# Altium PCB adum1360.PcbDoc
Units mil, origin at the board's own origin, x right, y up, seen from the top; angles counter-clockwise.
Board outline 2370 x 1680 mil, 2 copper layers (Top Layer, Bottom Layer); 20 components, 16 nets, 69 pads, 14 vias.
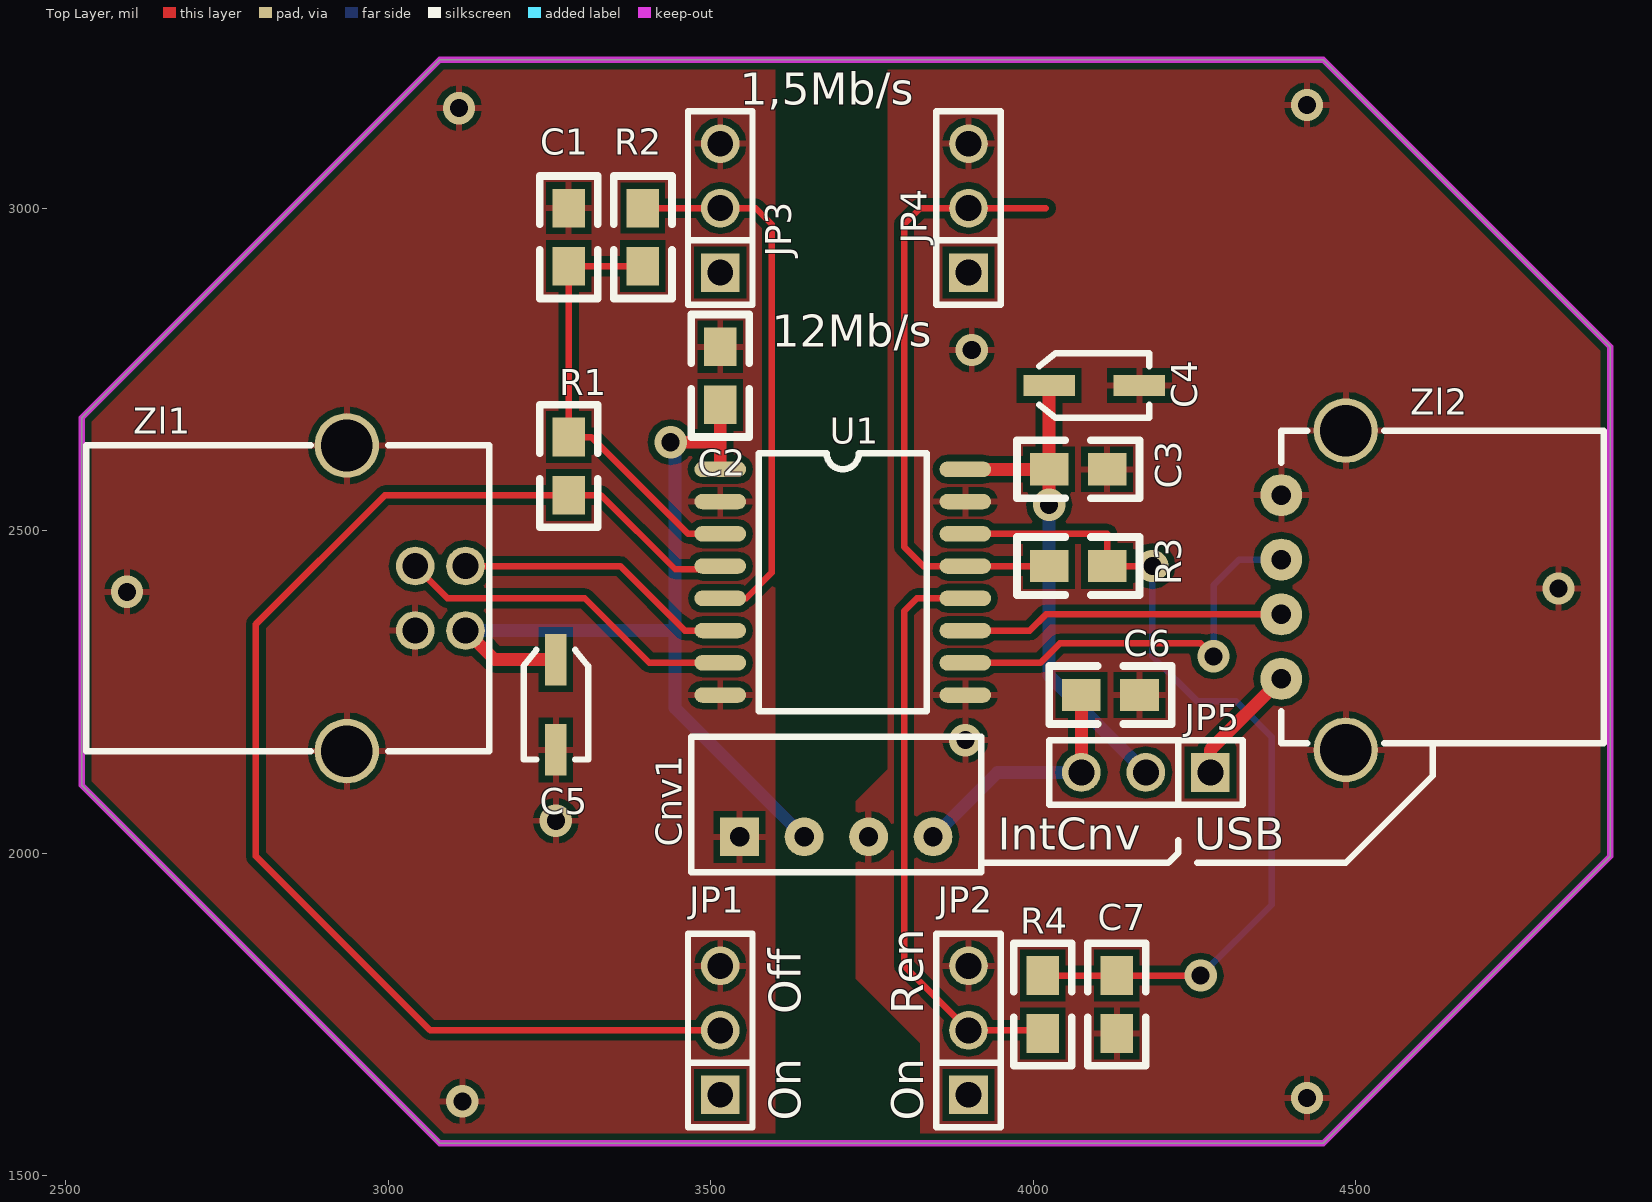
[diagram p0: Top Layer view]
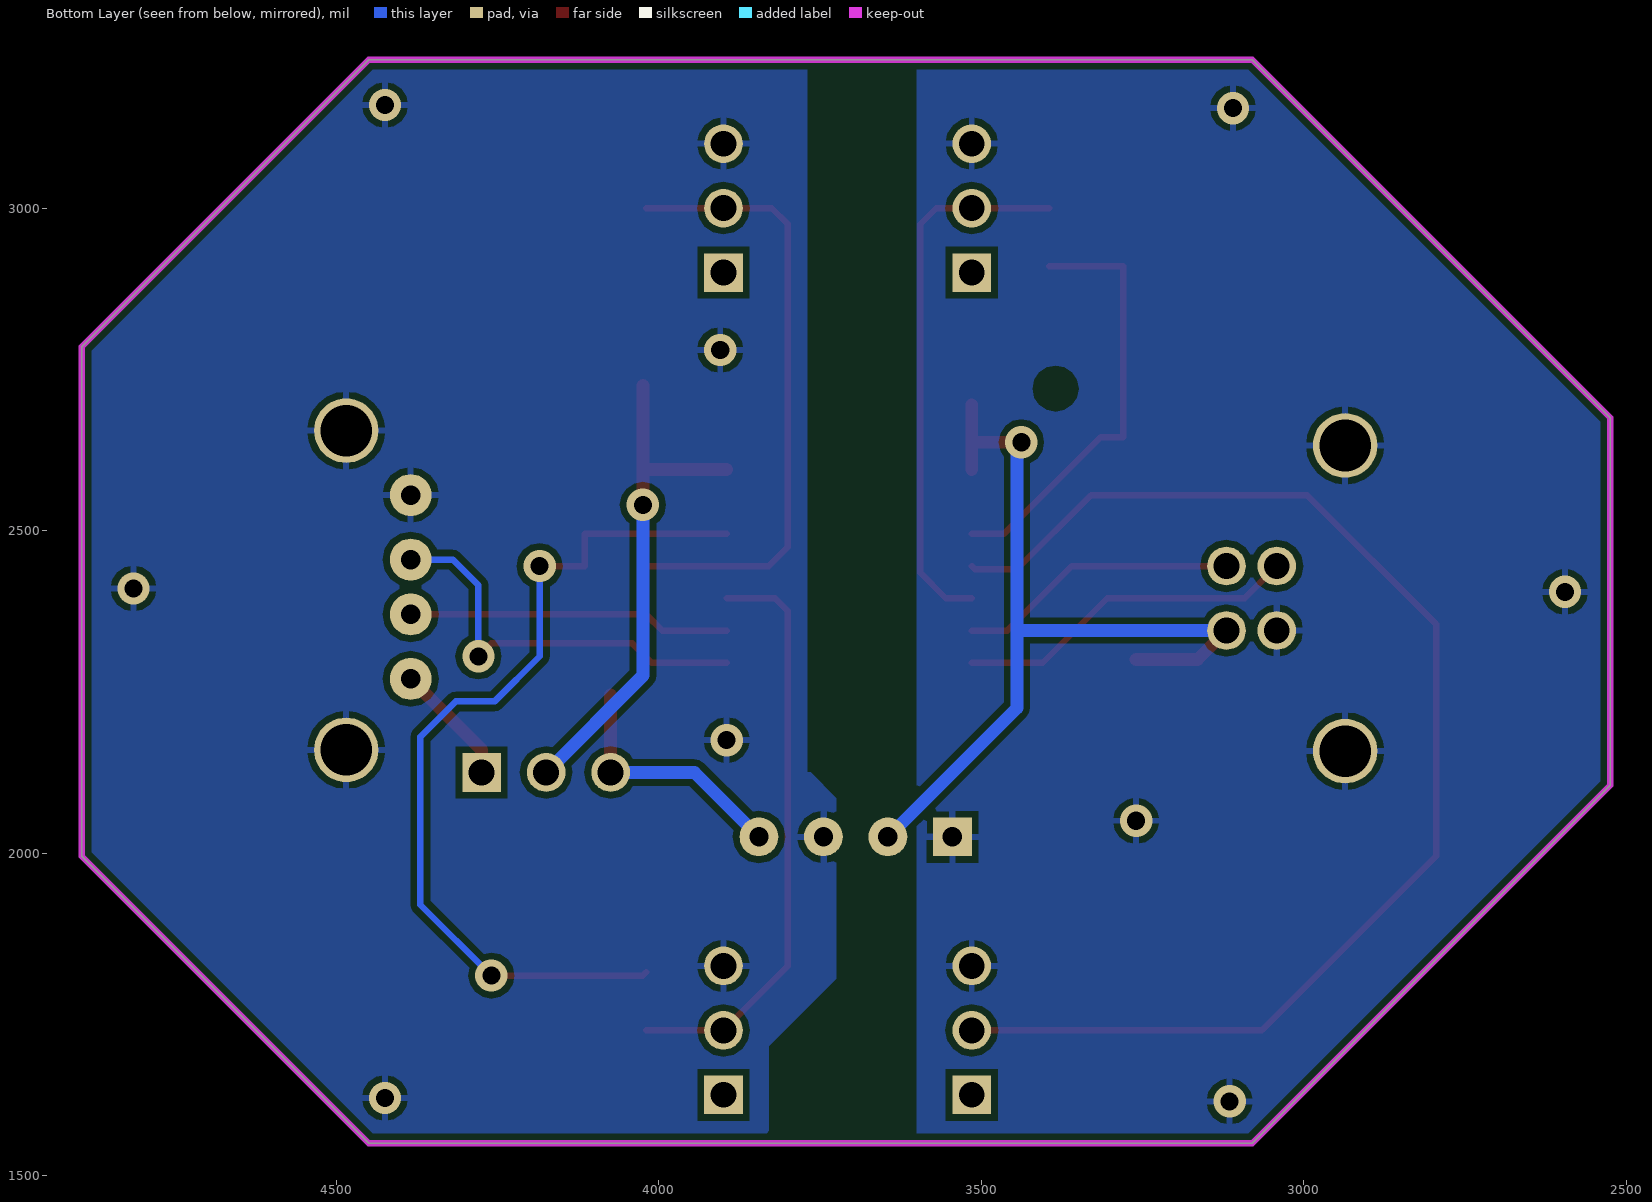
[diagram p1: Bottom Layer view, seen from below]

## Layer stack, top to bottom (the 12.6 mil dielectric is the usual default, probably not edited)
Top Layer: signal copper 1.4
Dielectric: dielectric 12.6, FR-4, Dk 4.8
Bottom Layer: signal copper 1.4

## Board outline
2525,2105 2525,2675 3080,3230 4450,3230 4895,2785 4895,1995 4450,1550 3080,1550

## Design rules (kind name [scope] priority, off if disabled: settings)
Clearance [All] p1: gap=10
PolygonConnect [All] p1: connectstyle=Relief reliefconductorwidth=10 reliefentries=4 polygonreliefangle="90 Angle"
RoutingVias [All] p1: holewidth=28 width=50 viastyle="Through Hole" minholewidth=28 minwidth=50 maxholewidth=28 maxwidth=50
SilkscreenOverComponentPads [All] p1: minsilkscreentomaskgap=10
SolderMaskExpansion [All] p1: expansion=4
Width Width_1 [InNet('VCC1')] p1: maxlimit=20 minlimit=15 preferedwidth=20
Width [InNet('VCC1')] p2: maxlimit=12 minlimit=10 preferedwidth=12 minimp=50.000000 maximp=50.000000 favimp=50.000000
27 further rules are at their usual default settings.

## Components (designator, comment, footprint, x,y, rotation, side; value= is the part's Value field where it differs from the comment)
C1 "100nF" 0805 3280,3000 r270 top
C2 "100nF" 0805 3515,2785 r270 top
C3 "100nF" 0805 4115,2595 r180 top
C4 "10uF" CE_SMD_W 4025,2725 r0 top
C5 "10uF" CE_SMD_W 3260,2300 r270 top
C6 "100nF" 0805 4165,2245 r180 top
C7 "100nF" 0805 4130,1810 r270 top
Cnv1 "AM1S-0505SZ" SIP4_AM1S 3545,2025 r0 top
JP1 "JP" sip-3 3515,1625 r90 top
JP2 "JP" sip-3 3900,1625 r90 top
JP3 "JP" sip-3 3515,2900 r90 top
JP4 "JP" sip-3 3900,2900 r90 top
JP5 "JP" sip-3 4275,2125 r180 top
R1 "10k" 0805 3280,2555 r90 top
R2 "10k" 0805 3395,3000 r270 top
R3 "10k" 0805 4025,2445 r0 top
R4 "10k" 0805 4015,1720 r90 top
U1 "ADUM3160" SOL-16 3515,2595 r0 top
Zl1 "USB_B" USB_B 3120,2345 r180 top
Zl2 "USB_A" USB_A 4385,2270 r0 top

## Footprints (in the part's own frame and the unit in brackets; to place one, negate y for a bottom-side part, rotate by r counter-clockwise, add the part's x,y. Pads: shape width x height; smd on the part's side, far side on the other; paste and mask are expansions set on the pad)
0805 [mil]
  rect 60x50 smd: 1(0,0) 2(90,0)
  silkscreen extent -50,-45 140,45
CE_SMD_W [mil]
  rect 80x33 smd: 1(0,0) 2(140,0)
  silkscreen extent -15,-50 155,50
SIP4_AM1S [mil]
  rect 60x60 hole 30: 1(0,0)
  round 60 hole 30: 2(100,0) 3(200,0) 4(300,0)
  silkscreen extent -75,-55 375,155
sip-3 [mil]
  rect 60x60 hole 40: 1(0,0)
  round 60 hole 40: 2(100,0) 3(200,0)
  silkscreen extent -50,-50 250,50
SOL-16 [mil]
  oval 80x24 smd: 1(0,0) 2(0,-50) 3(0,-100) 4(0,-150) 5(0,-200) 6(0,-250) 7(0,-300) 8(0,-350) 9(380,-350) 10(380,-300) 11(380,-250) 12(380,-200) 13(380,-150) 14(380,-100) 15(380,-50) 16(380,0)
  silkscreen extent 60,-375 320,25
USB_A [mil]
  round 65 hole 30: 1(0,0) 2(0,100) 3(0,185) 4(0,285)
  round 100 hole 80: 5(100,-110) 6(100,385)
  silkscreen extent 0,-100 500,385
USB_B [mil]
  round 60 hole 40: 1(0,0) 2(0,-100) 3(78,-100) 4(78,0)
  round 100 hole 80: 5(184,187) 6(184,-287)
  silkscreen extent -37,-287 588,187

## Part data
C1 C3 C7: library part CAP, "Capacitor"
C2 C6: library part Cap, "Capacitor"
C4 C5: library part CP, "Capacitor"
JP1 JP2 JP3 JP4 JP5: "Jumper"
R1 R2 R3 R4: library part RES2
Zl1: library part USB_A

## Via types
v1: diameter 50, hole 28, Top Layer to Bottom Layer, tented both sides, 11 vias
v2: diameter 50, hole 28, Top Layer to Bottom Layer, 3 vias

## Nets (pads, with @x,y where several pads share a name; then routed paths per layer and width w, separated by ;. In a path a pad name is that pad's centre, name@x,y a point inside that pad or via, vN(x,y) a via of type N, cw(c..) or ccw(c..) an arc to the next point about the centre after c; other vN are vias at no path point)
GND1: C1.1 C2.1 C5.2 Cnv1.1 JP1.3 JP3.3 U1.2 U1.8 Zl1.4 Zl1.5 Zl1.6
  other v1: 3115,1615 3260,2050 2595,2405 3110,3155
GND2: C3.1 C4.2 C6.1 C7.2 Cnv1.3 JP2.3 JP4.3 U1.9 U1.15 Zl2.4 Zl2.5 Zl2.6
  other v1: 4425,1620 3895,2175 4815,2410 3905,2780 4425,3160
NetC6_2: C6.2 Cnv1.4 JP5.3 | length 391.4
  Top Layer w20: JP5.3 C6.2
  Bottom Layer w20: Cnv1.4 3945,2125 JP5.3
NetJP5_1: JP5.1 Zl2.1 | length 190.6
  Top Layer w20: JP5.1 4275,2160 Zl2.1
NetU1_6: U1.6 Zl1.2 | length 436.4
  Top Layer w10: Zl1.2 3360,2445 3460,2345 U1.6
NetU1_7: U1.7 Zl1.3 | length 535.1
  Top Layer w10: Zl1.3 3092,2395 3305,2395 3405,2295 U1.7
NetU1_10: U1.10 Zl2.3 | length 622.3
  Top Layer w10: U1.10 4011.63,2295 4041.63,2325 4260,2325 v1(4280,2305)
  Bottom Layer w10: v1@4280,2320 4280,2415 4320,2455 Zl2.3
NetU1_11: U1.11 Zl2.2 | length 500.4
  Top Layer w10: U1.11 3995,2345 4020,2370 Zl2.2
PDEN: JP1.2 R1.1 U1.4 | length 2044.4
  Top Layer w10: JP1.2 3395,1725 3065,1725 2795,1995 2795,2355 2995,2555 3330,2555 3445,2440 3510,2440 U1.4
PIN: JP2.2 R4.1 U1.12 | length 914.7
  Top Layer w10: U1.12 3820,2395 3800,2375 3800,1825 JP2.2 R4.1@4020,1725
SPD: JP4.2 R3.1 U1.13 | length 967.8
  Top Layer w10: 4020,3000 JP4.2 3825,3000 3800,2975 3800,2475 3830,2445 U1.13 R3.1
SPU: JP3.2 R2.1 U1.5 | length 847
  Top Layer w10: R2.1 JP3.2 3570,3000 3595,2975 3595,2434.86 3555.14,2395 U1.5
VCC1: C2.2 C5.1 Cnv1.2 U1.1 Zl1.1 | length 1359.4
  Top Layer w20: Zl1.1 3165,2300 C5.1 ; v2(3438.16,2637) 3512,2637 3515,2640 ; U1.1 3515,2640 ; C2.2 3515,2640
  Bottom Layer w20: Zl1.1 3445,2345 ; v2(3438.16,2637) 3445,2630.16 3445,2345 ; Cnv1.2 3445,2225 3445,2345
VCC2: C3.2 C4.1 JP5.2 U1.16 | length 817.1
  Top Layer w10: C4.1@4020,2725 C4.1
  Top Layer w20: U1.16 C3.2 ; v1(4025,2540) 4025,2530 C3.2 ; C4.1 C3.2
  Bottom Layer w20: v1(4025,2540) 4025,2275 JP5.2
VDD1: C1.2 R1.2 R2.2 U1.3 | length 677.1
  Top Layer w10: R2.2 C1.2 R1.2 3315,2645 3465,2495 U1.3
VDD2: C7.1 R3.2 R4.2 U1.14 | length 1374.4
  Top Layer w10: U1.14 4115,2495 R3.2 v2(4185,2445) ; R4.2@4020,1815 4025,1810 C7.1 v2(4260,1810)
  Bottom Layer w10: v2(4185,2445) 4185,2305 4255,2235 4315,2235 4370,2180 4370,1920 v2(4260,1810)
pads on no net: JP1.1 JP2.1 JP3.1 JP4.1

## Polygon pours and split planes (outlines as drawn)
GND1 on Top Layer "Top Layer-No Net" (solid, pour order 2): 3600,3230 3600,1550 3080,1550 2525,2105 2525,2675 3085,3235 3090,3235 3595,3235 3600,3230
GND2 on Top Layer "Top Layer-No Net" (solid, pour order 4): 3775,3230 3775,2225 3775,2130 3725,2080 3725,1820 3725,1805 3825,1705 3825,1550 4450,1550 4895,1995 4895,2785 4450,3230
GND1 on Bottom Layer "Top Layer-No Net" (solid, pour order 8): 3600,1550 3600,3230 3080,3230 2525,2675 2525,2105 2530,2105 3085,1550 3600,1550
GND2 on Bottom Layer "Top Layer-No Net" (solid, pour order 6): 3825,1550 4450,1550 4455,1555 4895,1995 4895,2785 4450,3230 3775,3230 3770,3225 3770,2125 3765,2125 3725,2085 3725,1805 3825,1705 3830,1700 3830,1570

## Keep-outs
Keep-Out Layer:
  the board outline again, w10

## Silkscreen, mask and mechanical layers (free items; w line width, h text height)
Top Overlay:
  drawing of 58 lines, arcs and shapes, not listed
  text "1,5Mb/s" at 3545,3160 h50
  text "12Mb/s" at 3595,2785 h50
  text "IntCnv" at 3945,2005 h50
  text "USB" at 4250,2005 h50
  text "Off" at 3640,1750 h50 r90
  text "Ren" at 3830,1750 h50 r90
  text "On" at 3640,1585 h50 r90
  text "On" at 3830,1585 h50 r90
